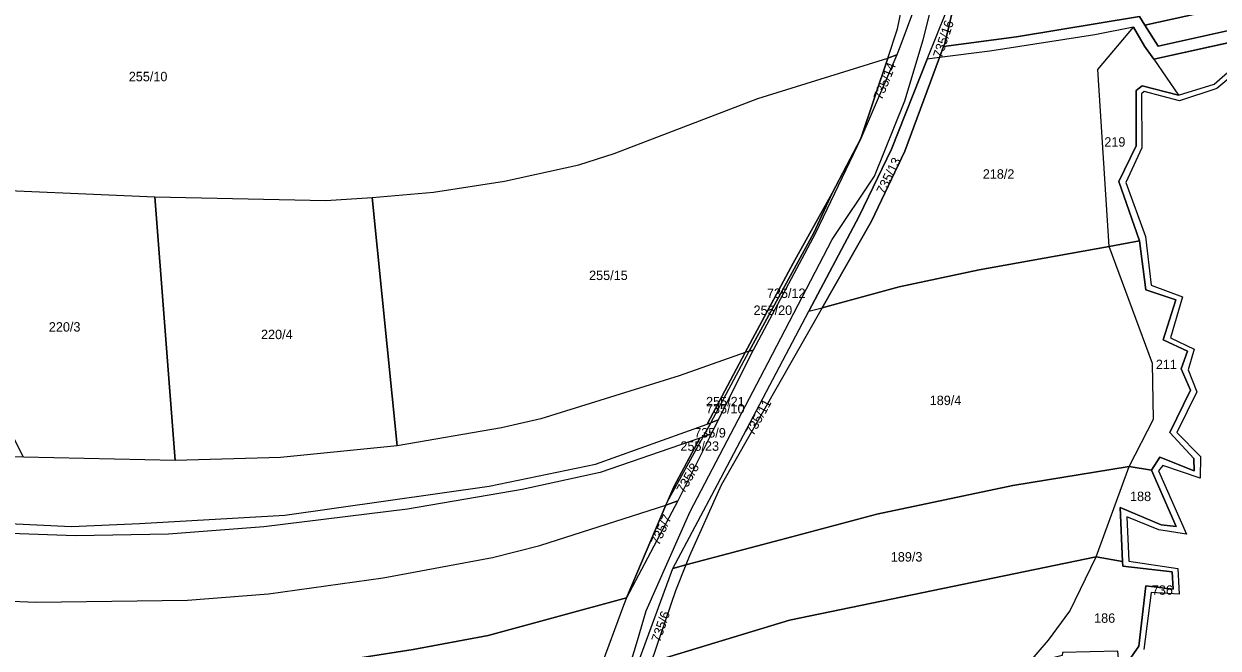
# Model space of a CAD drawing. Extents: x -629983 to -626385, y -1072828 to -1067897.
# Drawn here: x -628290.3 to -627910.7, y -1071357.1 to -1071158.6 of the extents above; entities that cross this region are included whole.
import ezdxf

# ---------------------------------------------------------------- set-up
doc = ezdxf.new("R2010")
doc.units = 0
for name, color, linetype in [('Parcela nároku', 7, 'Continuous'), ('Parcelní číslo', 7, 'Continuous'), ('Plocha PÚ', 7, 'Continuous'), ('silnice III třídy', 7, 'Continuous'), ('Šetřený obvod', 7, 'Continuous')]:
    doc.layers.add(name, color=color, linetype=linetype)

msp = doc.modelspace()

# ---------------------------------------------------------------- linework, layer by layer
at = {"layer": 'Parcela nároku'}
for points in [[(-628015.73, -1071169.53), (-628012.61, -1071160.21), (-628009.43, -1071144.65), (-628002.73, -1071117.73), (-627997.17, -1071082.8), (-627993.62, -1071081.37), (-627999.02, -1071119.3), (-628007.2, -1071153.48), (-628011.91, -1071165.98), (-628012.78, -1071168.42)], [(-627752.84, -1071100.75), (-627749.21, -1071113.14), (-627757.69, -1071122.93), (-627767.04, -1071125.4), (-627832.57, -1071137.81), (-627879.46, -1071146.9), (-627933.97, -1071158.98), (-627935.72, -1071156.2), (-627974.83, -1071162.69), (-627997.97, -1071165.82), (-627997.58, -1071164.78), (-627995.06, -1071154.04), (-627933.16, -1071141.74), (-627875.8, -1071126.47)], [(-627736.3, -1071127.78), (-627737.44, -1071125.68), (-627741.45, -1071118.06), (-627749.79, -1071120.85), (-627757.69, -1071122.93), (-627767.04, -1071125.4), (-627766.57, -1071128.76), (-627765.97, -1071133.05), (-627776.97, -1071138.89), (-627850.06, -1071151.85), (-627931.16, -1071169.85), (-627923.29, -1071181.28), (-627911.9, -1071177.74), (-627899.94, -1071167.3), (-627877.47, -1071175.35), (-627858.81, -1071169.49), (-627849.93, -1071180.53), (-627839, -1071184.17), (-627809.61, -1071172.49), (-627796.88, -1071168.78), (-627790.2, -1071162.76), (-627773.61, -1071166.4), (-627756.24, -1071156.55), (-627743.42, -1071131)], [(-627767.04, -1071125.4), (-627766.57, -1071128.76), (-627780.21, -1071136.17), (-627851.99, -1071147.88), (-627881.15, -1071154.85), (-627929.78, -1071165.66), (-627933.97, -1071158.98), (-627879.46, -1071146.9), (-627832.57, -1071137.81)], [(-627851.99, -1071147.88), (-627780.21, -1071136.17), (-627766.57, -1071128.76), (-627765.97, -1071133.05), (-627776.97, -1071138.89), (-627850.06, -1071151.85), (-627931.16, -1071169.85), (-627934.12, -1071165.68), (-627937.56, -1071159.66), (-627949.84, -1071162.09), (-627983.26, -1071167.23), (-627999.24, -1071169.27), (-627997.97, -1071165.82), (-627974.83, -1071162.69), (-627935.72, -1071156.2), (-627933.97, -1071158.98), (-627929.78, -1071165.66), (-627881.15, -1071154.85)], [(-628003.2, -1071169.86), (-627997.08, -1071154.52), (-627995.06, -1071154.04), (-627997.58, -1071164.78), (-627997.97, -1071165.82), (-627999.24, -1071169.27)], [(-627945.37, -1071229.34), (-627948.9, -1071173.13), (-627937.56, -1071159.66), (-627949.84, -1071162.09), (-627983.26, -1071167.23), (-627999.24, -1071169.27), (-628010.25, -1071199.05), (-628020.85, -1071221.29), (-628036.57, -1071248.86), (-628012.03, -1071242.26), (-627986.66, -1071236.86)], [(-627948.9, -1071173.13), (-627937.56, -1071159.66), (-627934.12, -1071165.68), (-627931.16, -1071169.85), (-627923.29, -1071181.28), (-627934.83, -1071178.27), (-627936.76, -1071179.75), (-627936.72, -1071197.34), (-627942.25, -1071208.7), (-627935.64, -1071227.57), (-627945.37, -1071229.34)], [(-628015.73, -1071169.53), (-628012.78, -1071168.42), (-628024.27, -1071195.07)], [(-628179.61, -1071213.84), (-628160.06, -1071212.14), (-628137.49, -1071208.61), (-628113.94, -1071203.38), (-628102.68, -1071199.86), (-628056.97, -1071182.3), (-628015.73, -1071169.53), (-628024.27, -1071195.07), (-628033.35, -1071212.44), (-628045.74, -1071234.71), (-628061.01, -1071263.12), (-628082.05, -1071270.57), (-628126.01, -1071284.19), (-628138.45, -1071287.1), (-628171.64, -1071292.78)], [(-628003.2, -1071169.86), (-628014.53, -1071198.43), (-628024.76, -1071219.72), (-628040.77, -1071249.92), (-628036.57, -1071248.86), (-628020.85, -1071221.29), (-628010.25, -1071199.05), (-627999.24, -1071169.27)], [(-628039.19, -1071225.02), (-628033.35, -1071212.44), (-628024.27, -1071195.07), (-628038.64, -1071225.14), (-628058.44, -1071262.34), (-628059.74, -1071262.67)], [(-628248.73, -1071213.64), (-628242.24, -1071297.42), (-628290.4, -1071296.4), (-628334.96, -1071209.11), (-628312.3, -1071210.8)], [(-628194.33, -1071214.81), (-628179.61, -1071213.84), (-628171.64, -1071292.78), (-628208.79, -1071296.49), (-628242.24, -1071297.42), (-628248.73, -1071213.64)], [(-628061.01, -1071263.12), (-628045.74, -1071234.71), (-628033.35, -1071212.44), (-628039.19, -1071225.02), (-628059.74, -1071262.67)], [(-627931.24, -1071284.35), (-627931.58, -1071266.64), (-627945.37, -1071229.34), (-627986.66, -1071236.86), (-628012.03, -1071242.26), (-628036.57, -1071248.86), (-628068.69, -1071305.28), (-628078.68, -1071327.73), (-628079.84, -1071330.64), (-628046.2, -1071321.71), (-628019.15, -1071314.57), (-627975.97, -1071305.36), (-627938.98, -1071299.39)], [(-627928.12, -1071259.12), (-627920.4, -1071262.66), (-627922.39, -1071268.34), (-627919.52, -1071275.09), (-627926.05, -1071288.6), (-627918.45, -1071296.81), (-627918.25, -1071300.75), (-627929.23, -1071296.44), (-627931.91, -1071300.57), (-627938.98, -1071299.39), (-627931.24, -1071284.35), (-627931.58, -1071266.64), (-627945.37, -1071229.34), (-627935.64, -1071227.57), (-627933.65, -1071243.21), (-627924.16, -1071246.4)], [(-628069.8, -1071305.07), (-628040.77, -1071249.92), (-628036.57, -1071248.86), (-628068.69, -1071305.28), (-628078.68, -1071327.73), (-628079.84, -1071330.64), (-628084.03, -1071331.8)], [(-628208.79, -1071296.49), (-628242.24, -1071297.42), (-628290.4, -1071296.4), (-628316.82, -1071295.58), (-628364.74, -1071292.65), (-628427.39, -1071287.11), (-628467.03, -1071283.14), (-628517.75, -1071280.56), (-628524.42, -1071298.51), (-628482.04, -1071301.6), (-628438.06, -1071305.8), (-628395.02, -1071310.8), (-628365.42, -1071314.12), (-628275.13, -1071318.47), (-628253.61, -1071317.5), (-628207.37, -1071314.88), (-628142.44, -1071305.66), (-628108.62, -1071298.61), (-628073.11, -1071285.89), (-628061.01, -1071263.12), (-628082.05, -1071270.57), (-628126.01, -1071284.19), (-628138.45, -1071287.1), (-628171.64, -1071292.78)], [(-628059.74, -1071262.67), (-628061.01, -1071263.12), (-628073.11, -1071285.89), (-628071.96, -1071285.48)], [(-628059.74, -1071262.67), (-628058.44, -1071262.34), (-628069.63, -1071284.56), (-628071.96, -1071285.48)], [(-628071.96, -1071285.48), (-628069.63, -1071284.56), (-628071.71, -1071288.84), (-628074.34, -1071289.93)], [(-628107.14, -1071301.3), (-628131.89, -1071306.72), (-628168.32, -1071312.98), (-628214.06, -1071318.59), (-628244.37, -1071320.84), (-628273.93, -1071321.45), (-628318.54, -1071319.86), (-628371.43, -1071316.29), (-628440.08, -1071308.56), (-628526.04, -1071301.81), (-628534.77, -1071322.4), (-628437.67, -1071331.83), (-628361.69, -1071338.57), (-628328.43, -1071340.82), (-628286.36, -1071342.53), (-628238.25, -1071341.91), (-628212.54, -1071339.87), (-628176.11, -1071334.77), (-628141.31, -1071328.32), (-628126.29, -1071324.47), (-628086.27, -1071311.66), (-628085.77, -1071310.46), (-628083.67, -1071305.78), (-628075.46, -1071290.32)], [(-628074.34, -1071289.93), (-628071.71, -1071288.84), (-628082.46, -1071310.3), (-628086.27, -1071311.66), (-628085.77, -1071310.46)], [(-628083.67, -1071305.78), (-628085.77, -1071310.46), (-628074.34, -1071289.93), (-628075.46, -1071290.32)], [(-628046.2, -1071321.71), (-628079.84, -1071330.64), (-628083.15, -1071338.94), (-628090.87, -1071361.64), (-628046.95, -1071348.21), (-627949.41, -1071328.06), (-627938.98, -1071299.39), (-627975.97, -1071305.36), (-628019.15, -1071314.57)], [(-627931.91, -1071300.57), (-627924.05, -1071318.41), (-627928.74, -1071317.87), (-627941.81, -1071312.4), (-627941.08, -1071329.53), (-627949.41, -1071328.06), (-627938.98, -1071299.39)], [(-628361.69, -1071338.57), (-628328.43, -1071340.82), (-628286.36, -1071342.53), (-628238.25, -1071341.91), (-628212.54, -1071339.87), (-628176.11, -1071334.77), (-628141.31, -1071328.32), (-628126.29, -1071324.47), (-628086.27, -1071311.66), (-628098.7, -1071341.18), (-628142.69, -1071353.16), (-628166.54, -1071357.54), (-628240.16, -1071369.08), (-628261.61, -1071371.41), (-628280.79, -1071372.47), (-628329.76, -1071373.7), (-628347.75, -1071374.26), (-628358.35, -1071374.06), (-628401.12, -1071368.15), (-628538.52, -1071351.85), (-628535.81, -1071326.91), (-628534.77, -1071322.4), (-628437.67, -1071331.83)], [(-628098.7, -1071341.18), (-628086.27, -1071311.66), (-628082.46, -1071310.3)], [(-628094.62, -1071372.65), (-628100.9, -1071401.29), (-628102.28, -1071406.24), (-628050.02, -1071390.94), (-627971.19, -1071362.27), (-627964.59, -1071354.59), (-627957.78, -1071345.38), (-627949.41, -1071328.06), (-628046.95, -1071348.21), (-628090.87, -1071361.64)], [(-627949.41, -1071328.06), (-627941.08, -1071329.53), (-627941.01, -1071331.11), (-627925.28, -1071332.86), (-627924.96, -1071338.43), (-627933.65, -1071337.34), (-627935.92, -1071356.51), (-627941.95, -1071365.24), (-627942.52, -1071358.07), (-627960.14, -1071358.49), (-627960.21, -1071359.46), (-627971.19, -1071362.27), (-627964.59, -1071354.59), (-627957.78, -1071345.38)], [(-628095.5, -1071362.98), (-628084.03, -1071331.8), (-628079.84, -1071330.64), (-628083.15, -1071338.94), (-628090.87, -1071361.64)]]:
    msp.add_lwpolyline(points, close=True, dxfattribs=at)
for points in [[(-628312.3, -1071210.8), (-628248.73, -1071213.64), (-628194.33, -1071214.81), (-628179.61, -1071213.84), (-628160.06, -1071212.14), (-628137.49, -1071208.61), (-628113.94, -1071203.38), (-628102.68, -1071199.86), (-628056.97, -1071182.3), (-628015.73, -1071169.53), (-628012.61, -1071160.21), (-628009.43, -1071144.65), (-628002.73, -1071117.73), (-627997.17, -1071082.8), (-627998.39, -1071083.26), (-628024.12, -1071092.92), (-628055.43, -1071105.33), (-628115.45, -1071131.14), (-628133.98, -1071135.16), (-628174.24, -1071140.74), (-628189.96, -1071141.09), (-628268.25, -1071136.94), (-628291.93, -1071135.53)], [(-628007.2, -1071153.48), (-628011.91, -1071165.98), (-628012.78, -1071168.42), (-628024.27, -1071195.07), (-628038.64, -1071225.14), (-628058.44, -1071262.34), (-628069.63, -1071284.56), (-628071.71, -1071288.84), (-628082.46, -1071310.3), (-628098.7, -1071341.18), (-628099.72, -1071343.62), (-628107.26, -1071363.88)], [(-628095.5, -1071362.98), (-628084.03, -1071331.8), (-628069.8, -1071305.07), (-628040.77, -1071249.92), (-628024.76, -1071219.72), (-628014.53, -1071198.43), (-628003.2, -1071169.86), (-627997.08, -1071154.52)], [(-627941.95, -1071365.24), (-627935.92, -1071356.51), (-627933.65, -1071337.34), (-627924.96, -1071338.43), (-627925.28, -1071332.86), (-627941.01, -1071331.11), (-627941.08, -1071329.53), (-627941.81, -1071312.4), (-627928.74, -1071317.87), (-627924.05, -1071318.41), (-627931.91, -1071300.57), (-627929.23, -1071296.44), (-627918.25, -1071300.75), (-627918.45, -1071296.81), (-627926.05, -1071288.6), (-627919.52, -1071275.09), (-627922.39, -1071268.34), (-627920.4, -1071262.66), (-627928.12, -1071259.12), (-627924.16, -1071246.4), (-627933.65, -1071243.21), (-627935.64, -1071227.57), (-627942.25, -1071208.7), (-627936.72, -1071197.34), (-627936.76, -1071179.75), (-627934.83, -1071178.27), (-627923.29, -1071181.28), (-627911.9, -1071177.74), (-627899.94, -1071167.3)], [(-627899.26, -1071169.31), (-627911.13, -1071179.09), (-627922.94, -1071183.02), (-627934.18, -1071180.09), (-627935.05, -1071180.87), (-627934.9, -1071198.03), (-627940.05, -1071209.08), (-627933.77, -1071226.16), (-627931.97, -1071241.72), (-627922.04, -1071245.42), (-627925.85, -1071258.4), (-627918.32, -1071262.02), (-627920.16, -1071268.61), (-627917.48, -1071275.64), (-627923.78, -1071288.51), (-627916.29, -1071296.23), (-627916.38, -1071303.07), (-627928.25, -1071299.01), (-627929.62, -1071300.79), (-627920.75, -1071320.85), (-627929.56, -1071319.54), (-627939.74, -1071315.36), (-627939.05, -1071329.51), (-627923.53, -1071331.79), (-627923.09, -1071339.94), (-627931.93, -1071339.48), (-627934.34, -1071357.54)], [(-628365.42, -1071314.12), (-628275.13, -1071318.47), (-628253.61, -1071317.5), (-628207.37, -1071314.88), (-628142.44, -1071305.66), (-628108.62, -1071298.61), (-628073.11, -1071285.89), (-628071.96, -1071285.48), (-628074.34, -1071289.93), (-628075.46, -1071290.32), (-628107.14, -1071301.3), (-628131.89, -1071306.72), (-628168.32, -1071312.98), (-628214.06, -1071318.59), (-628244.37, -1071320.84), (-628273.93, -1071321.45), (-628318.54, -1071319.86)], [(-628329.76, -1071373.7), (-628280.79, -1071372.47), (-628261.61, -1071371.41), (-628240.16, -1071369.08), (-628166.54, -1071357.54), (-628142.69, -1071353.16), (-628098.7, -1071341.18), (-628099.72, -1071343.62), (-628107.26, -1071363.88), (-628109.25, -1071372.92), (-628165.52, -1071384.33), (-628205.08, -1071390.76), (-628222.97, -1071393.4), (-628274.23, -1071399.23), (-628303.29, -1071400.24)]]:
    msp.add_lwpolyline(points, dxfattribs=at)
at = {"layer": 'Plocha PÚ'}
for points in [[(-627948.9, -1071173.13), (-627937.56, -1071159.66), (-627934.12, -1071165.68), (-627931.16, -1071169.85), (-627890.61, -1071160.85)], [(-627971.19, -1071362.27), (-627964.59, -1071354.59), (-627957.78, -1071345.38), (-627949.41, -1071328.06), (-627938.98, -1071299.39), (-627931.24, -1071284.35), (-627931.58, -1071266.64), (-627945.37, -1071229.34), (-627948.9, -1071173.13)]]:
    msp.add_lwpolyline(points, dxfattribs=at)
at = {"layer": 'silnice III třídy'}
msp.add_lwpolyline([(-628121.59, -1071462.69), (-628112.08, -1071419.34), (-628104.87, -1071386.48), (-628095.28, -1071354.66), (-628092.46, -1071345.32), (-628078.48, -1071313.67), (-628057.35, -1071273.18), (-628053.76, -1071266.3), (-628046.96, -1071253.26), (-628040.16, -1071240.22), (-628033.36, -1071227.18), (-628019.93, -1071206.98), (-628010.26, -1071183.04), (-628004.5, -1071163.61), (-628001.98, -1071154)], dxfattribs=at)
at = {"layer": 'Šetřený obvod'}
for p, q in [((-627948.9, -1071173.13), (-627937.56, -1071159.66)), ((-627937.56, -1071159.66), (-627934.12, -1071165.68)), ((-627931.16, -1071169.85), (-627890.61, -1071160.85)), ((-627934.12, -1071165.68), (-627931.16, -1071169.85)), ((-627945.37, -1071229.34), (-627948.9, -1071173.13)), ((-627931.58, -1071266.64), (-627945.37, -1071229.34)), ((-627931.24, -1071284.35), (-627931.58, -1071266.64)), ((-627938.98, -1071299.39), (-627931.24, -1071284.35)), ((-627949.41, -1071328.06), (-627938.98, -1071299.39)), ((-627957.78, -1071345.38), (-627949.41, -1071328.06)), ((-627964.59, -1071354.59), (-627957.78, -1071345.38)), ((-627971.19, -1071362.27), (-627964.59, -1071354.59))]:
    msp.add_line(p, q, dxfattribs=at)

# ---------------------------------------------------------------- texts
at = {"layer": 'Parcelní číslo'}
for s, rotation, p in [('735/16', 71.204, (-627998.59, -1071169.69)), ('735/14', 67.9931, (-628017.6, -1071183.03)), ('735/13', 63.8617, (-628016.79, -1071213.06)), ('735/11', 61.3895, (-628058.43, -1071289.78)), ('735/8', 60.4545, (-628080.46, -1071308.14)), ('735/7', 65.4704, (-628088.45, -1071324.65)), ('735/6', 71.0096, (-628088.12, -1071355.48))]:
    msp.add_text(s, height=3, rotation=rotation, dxfattribs=at).set_placement(p)
for s, p in [('255/10', (-628256.96, -1071176.83)), ('219', (-627946.86, -1071197.64)), ('218/2', (-627985.49, -1071207.83)), ('255/15', (-628110.64, -1071240.06)), ('735/12', (-628054.11, -1071245.76)), ('255/20', (-628058.36, -1071251.16)), ('220/3', (-628282.37, -1071256.46)), ('220/4', (-628214.93, -1071258.86)), ('211', (-627930.49, -1071268.4)), ('255/21', (-628073.46, -1071280.23)), ('189/4', (-628002.36, -1071279.83)), ('735/10', (-628073.49, -1071282.48)), ('735/9', (-628077.22, -1071290.14)), ('255/23', (-628081.61, -1071294.37)), ('188', (-627938.68, -1071310.36)), ('189/3', (-628014.73, -1071329.6)), ('736', (-627931.76, -1071340.15)), ('186', (-627950.1, -1071349.08))]:
    msp.add_text(s, height=3, dxfattribs=at).set_placement(p)

doc.saveas('drawing.dxf')
